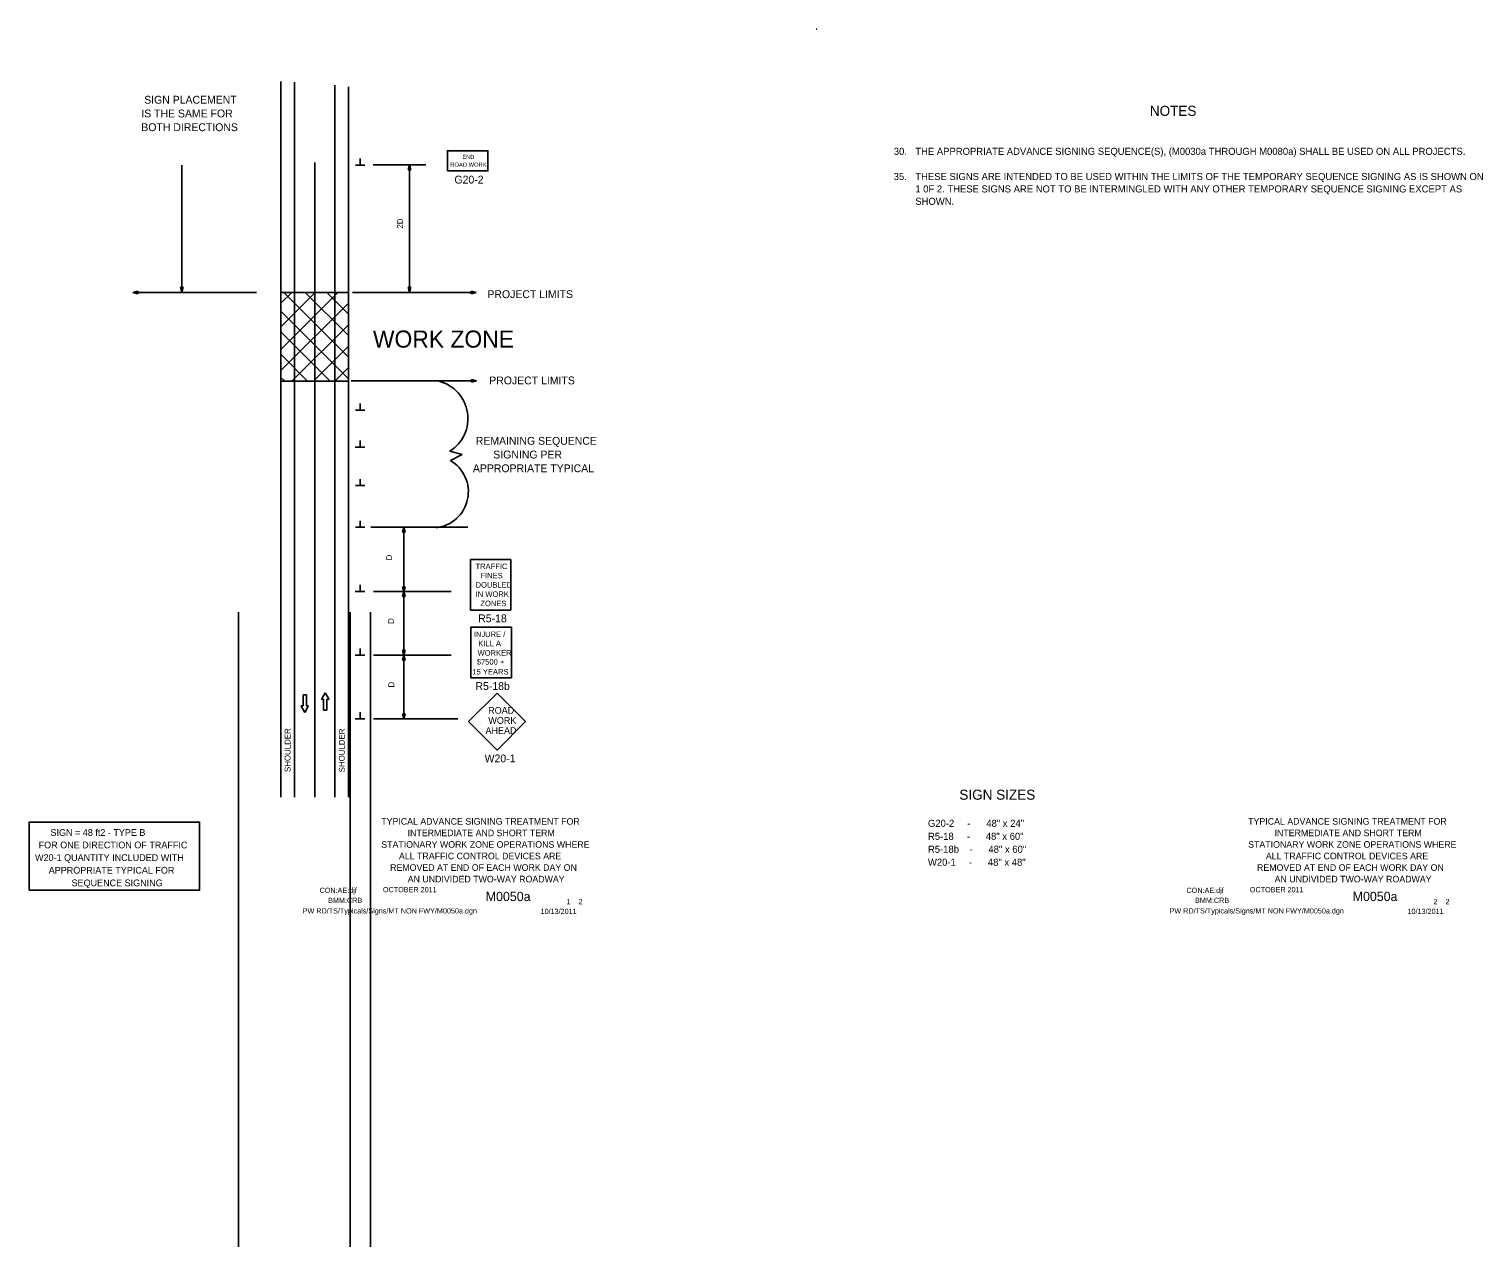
# Model space of a CAD drawing. Extents: x 16735 to 18461, y 5466 to 6911.
import ezdxf

# ---------------------------------------------------------------- set-up
doc = ezdxf.new("R2010")
doc.units = 0
for name, color, linetype in [('BORDER', 7, 'Continuous'), ('BORDER_SIGNAL_WO', 7, 'Continuous'), ('MT_SCRATCH_LEVEL_E', 7, 'Continuous'), ('PAVT_EDGE_EX', 7, 'Continuous'), ('TRAFFIC_SIGNS_PR', 7, 'Continuous'), ('TYPICAL_TEXT_DIMEN_PR', 7, 'Continuous')]:
    doc.layers.add(name, color=color, linetype=linetype)

msp = doc.modelspace()

# ---------------------------------------------------------------- linework, layer by layer
at = {"layer": 'BORDER'}
for p, q in [((17898.5, 5982.8), (17898.5, 5982.8)), ((17898.5, 5982.8), (17898.5, 5982.8)), ((17278, 5920.6), (17278, 5920.6))]:
    msp.add_line(p, q, dxfattribs=at)
at = {"layer": 'BORDER_SIGNAL_WO'}
msp.add_line((17670, 6911.2), (17669.5, 6911.3), dxfattribs=at)
at = {"layer": 'MT_SCRATCH_LEVEL_E'}
for p, q in [((17060.5, 6107.8), (17060.5, 6121)), ((17060.5, 6121), (17064.2, 6121)), ((17060.5, 6107.8), (17060.5, 6121)), ((17060.5, 6121), (17064.2, 6121)), ((17064.2, 6121), (17064.2, 6107.8)), ((17064.2, 6121), (17064.2, 6107.8)), ((17086.5, 6123.6), (17082.4, 6116.3)), ((17086.5, 6123.6), (17082.4, 6116.3)), ((17082.9, 6115.6), (17084.7, 6116)), ((17082.9, 6115.6), (17084.7, 6116)), ((17084.7, 6116), (17084.7, 6102.7)), ((17084.7, 6116), (17084.7, 6102.7)), ((17090.7, 6116.3), (17086.5, 6123.6)), ((17090.7, 6116.3), (17086.5, 6123.6)), ((17088.4, 6102.7), (17088.4, 6116)), ((17088.4, 6116), (17090.2, 6115.6)), ((17088.4, 6102.7), (17088.4, 6116)), ((17088.4, 6116), (17090.2, 6115.6)), ((17062.3, 6100.2), (17058.2, 6107.4)), ((17062.3, 6100.2), (17058.2, 6107.4)), ((17058.7, 6108.1), (17060.5, 6107.8)), ((17058.7, 6108.1), (17060.5, 6107.8)), ((17066.5, 6107.4), (17062.3, 6100.2)), ((17066.5, 6107.4), (17062.3, 6100.2)), ((17064.2, 6107.8), (17066, 6108.1)), ((17064.2, 6107.8), (17066, 6108.1)), ((17084.7, 6102.7), (17088.4, 6102.7)), ((17084.7, 6102.7), (17088.4, 6102.7))]:
    msp.add_line(p, q, dxfattribs=at)
for centre, start, end in [((17082.8, 6116.1), 150.4248, 279.9638), ((17082.8, 6116.1), 150.4248, 279.9638), ((17090.3, 6116.1), 260.0362, 29.7731), ((17090.3, 6116.1), 260.0362, 29.7731), ((17058.6, 6107.6), 80.0362, 209.5752), ((17058.6, 6107.6), 80.0362, 209.5752), ((17066.1, 6107.6), 330.2269, 99.9638), ((17066.1, 6107.6), 330.2269, 99.9638)]:
    msp.add_arc(centre, 0.463, start, end, dxfattribs=at)
at = {"layer": 'PAVT_EDGE_EX'}
for p, q in [((17034.1, 6849.3), (17034.1, 5999.6)), ((17050.1, 6848.5), (17050.1, 5999.6)), ((17098.1, 6844.8), (17098.1, 5999.6)), ((17114.1, 6842.6), (17114.1, 5999.6)), ((17050.1, 6753), (17050.1, 5999.6)), ((17074.1, 6753), (17074.1, 5999.6)), ((17114.1, 6598.8), (17034.1, 6598.8)), ((17034.1, 6586.1), (17046.8, 6598.8)), ((17034.1, 6557.8), (17074.8, 6598.6)), ((17034.6, 6531.8), (17101.6, 6598.8)), ((17114.1, 6522), (17037.1, 6599)), ((17114.1, 6547.5), (17062.5, 6599)), ((17114.1, 6572.9), (17088.4, 6598.7)), ((17098.1, 6599.3), (17098.1, 6493.5)), ((17114.1, 6598.4), (17113.7, 6598.8)), ((17114.1, 6493.5), (17114.1, 6598.8)), ((17114, 6496.6), (17033.7, 6577)), ((17034.5, 6506.3), (17114.1, 6585.9)), ((17047.3, 6493.6), (17114.1, 6560.4)), ((17092.2, 6493.6), (17034.4, 6551.5)), ((17065.7, 6493.5), (17034, 6525.3)), ((17072.6, 6493.5), (17114.1, 6534.9)), ((17098.1, 6493.5), (17114.1, 6509.5)), ((17033.6, 6493.5), (17114.1, 6493.5)), ((17038.2, 6493.7), (17034, 6497.9)), ((17098.1, 6493.5), (17114.1, 6493.5)), ((17098.1, 6493.5), (17098.1, 6493.5)), ((16983.7, 6219.1), (16983.7, 5465.7)), ((17116.3, 6219.1), (17116.3, 5465.7)), ((17140.3, 6219.1), (17140.3, 5465.7))]:
    msp.add_line(p, q, dxfattribs=at)
for points in [[(17050.1, 6753), (17050.1, 6728)], [(17074.1, 6753), (17074.1, 6728)], [(17074.1, 6653), (17074.1, 6628)], [(17074.1, 6453), (17074.1, 6428)], [(17074.1, 6353), (17074.1, 6328)], [(17074.1, 6253), (17074.1, 6228)], [(17050.1, 6153), (17050.1, 6128)], [(17074.1, 6153), (17074.1, 6128)], [(17050.1, 6053), (17050.1, 6028)], [(17074.1, 6053), (17074.1, 6028)]]:
    msp.add_lwpolyline(points, dxfattribs=at)
at = {"layer": 'TRAFFIC_SIGNS_PR'}
for p, q in [((17259, 6221.5), (17259, 6281.5)), ((17259, 6281.5), (17307, 6281.5)), ((17307, 6221.5), (17307, 6281.5)), ((17259, 6221.5), (17307, 6221.5)), ((17259.6, 6141.2), (17259.6, 6201.2)), ((17307.6, 6201.2), (17259.6, 6201.2)), ((17307.6, 6141.2), (17307.6, 6201.2)), ((17307.6, 6141.2), (17259.6, 6141.2)), ((17290.6, 6123.1), (17256.7, 6089.2)), ((17324.5, 6089.2), (17290.6, 6123.1)), ((17256.7, 6089.2), (17290.6, 6055.2)), ((17290.6, 6055.2), (17324.5, 6089.2))]:
    msp.add_line(p, q, dxfattribs=at)
at = {"layer": 'TYPICAL_TEXT_DIMEN_PR'}
for p, q in [((16916.5, 6749.9), (16916.5, 6599.1)), ((17128.1, 6749.8), (17122.5, 6749.8)), ((17128.1, 6749.8), (17128.1, 6757.6)), ((17133.7, 6749.8), (17128.1, 6749.8)), ((17143.5, 6750), (17205.9, 6750)), ((17185, 6744.2), (17186.6, 6750.1)), ((17186.5, 6749.9), (17186.5, 6599.1)), ((17186.6, 6750.1), (17188.1, 6744.2)), ((17186.6, 6744.2), (17185, 6744.2)), ((17188.1, 6744.2), (17186.6, 6744.2)), ((16864.1, 6600.4), (16858.2, 6598.8)), ((17005, 6598.8), (16858.2, 6598.8)), ((16858.2, 6598.8), (16864.1, 6597.2)), ((16864.1, 6598.8), (16864.1, 6600.4)), ((16864.1, 6597.2), (16864.1, 6598.8)), ((16916.5, 6599.1), (16914.9, 6605)), ((16914.9, 6605), (16916.5, 6605)), ((16916.5, 6605), (16918.1, 6605)), ((16918.1, 6605), (16916.5, 6599.1)), ((17119, 6598.8), (17265.8, 6598.8)), ((17186.6, 6598.9), (17185, 6604.8)), ((17185, 6604.8), (17186.6, 6604.8)), ((17186.6, 6604.8), (17188.1, 6604.8)), ((17188.1, 6604.8), (17186.6, 6598.9)), ((17259.9, 6598.8), (17259.9, 6600.4)), ((17259.9, 6600.4), (17265.8, 6598.8)), ((17265.8, 6598.8), (17259.9, 6597.2)), ((17259.9, 6597.2), (17259.9, 6598.8)), ((17117.5, 6493.9), (17266.2, 6493.9)), ((17260.4, 6493.9), (17260.4, 6495.4)), ((17260.4, 6495.4), (17266.2, 6493.9)), ((17266.2, 6493.9), (17260.4, 6492.3)), ((17260.4, 6492.3), (17260.4, 6493.9)), ((17128.2, 6458.9), (17122.6, 6458.9)), ((17128.2, 6458.9), (17128.2, 6466.7)), ((17133.8, 6458.9), (17128.2, 6458.9)), ((17127.9, 6415), (17127.9, 6422.8)), ((17127.9, 6415), (17122.3, 6415)), ((17133.5, 6415), (17127.9, 6415)), ((17234.6, 6410.2), (17249.2, 6406.4)), ((17249.2, 6406.4), (17235.2, 6399.3)), ((17128.2, 6369.4), (17122.6, 6369.4)), ((17128.2, 6369.4), (17128.2, 6377.2)), ((17133.8, 6369.4), (17128.2, 6369.4)), ((17128.2, 6319.9), (17122.6, 6319.9)), ((17128.2, 6319.9), (17128.2, 6327.7)), ((17133.8, 6319.9), (17128.2, 6319.9)), ((17140.6, 6319.9), (17255.8, 6319.9)), ((17178.2, 6314.1), (17179.8, 6319.9)), ((17179.8, 6319.9), (17179.8, 6168.1)), ((17179.8, 6319.9), (17181.4, 6314.1)), ((17179.8, 6314.1), (17178.2, 6314.1)), ((17181.4, 6314.1), (17179.8, 6314.1)), ((17127.9, 6243.7), (17127.9, 6251.5)), ((17179.8, 6243.5), (17178.2, 6249.4)), ((17178.2, 6249.4), (17179.8, 6249.4)), ((17179.8, 6249.4), (17181.4, 6249.4)), ((17181.4, 6249.4), (17179.8, 6243.5)), ((17127.9, 6243.7), (17122.3, 6243.7)), ((17133.5, 6243.7), (17127.9, 6243.7)), ((17144, 6243.5), (17236.1, 6243.5)), ((17178.2, 6237.6), (17179.8, 6243.5)), ((17179.8, 6237.6), (17178.2, 6237.6)), ((17179.8, 6243.5), (17181.4, 6237.6)), ((17181.4, 6237.6), (17179.8, 6237.6)), ((17127.9, 6168.3), (17122.3, 6168.3)), ((17127.9, 6168.3), (17127.9, 6176.1)), ((17133.5, 6168.3), (17127.9, 6168.3)), ((17144, 6168.1), (17236.1, 6168.1)), ((17179.8, 6168.1), (17178.2, 6174)), ((17178.2, 6174), (17179.8, 6174)), ((17178.2, 6162.2), (17179.8, 6168.1)), ((17179.8, 6162.2), (17178.2, 6162.2)), ((17179.8, 6174), (17181.4, 6174)), ((17181.4, 6174), (17179.8, 6168.1)), ((17179.8, 6168.1), (17179.8, 6092.7)), ((17179.8, 6168.1), (17181.4, 6162.2)), ((17181.4, 6162.2), (17179.8, 6162.2)), ((17127.9, 6092.5), (17122.3, 6092.5)), ((17127.9, 6092.5), (17127.9, 6100.3)), ((17133.6, 6092.5), (17127.9, 6092.5)), ((17144, 6092.7), (17244.2, 6092.7)), ((17179.8, 6092.7), (17178.2, 6098.6)), ((17178.2, 6098.6), (17179.8, 6098.6)), ((17179.8, 6098.6), (17181.4, 6098.6)), ((17181.4, 6098.6), (17179.8, 6092.7))]:
    msp.add_line(p, q, dxfattribs=at)
for points in [[(17231.7, 6743), (17279.7, 6743), (17279.7, 6767), (17231.7, 6767)], [(16735.1, 5889.1), (16937.5, 5889.1), (16937.5, 5970), (16735.1, 5970)]]:
    msp.add_lwpolyline(points, close=True, dxfattribs=at)
for centre, radius, start, end in [((17210.2, 6449), 45.8, 302.1563, 75.2517), ((17213.6, 6362.1), 42.9, 276.3375, 59.9789)]:
    msp.add_arc(centre, radius, start, end, dxfattribs=at)

# ---------------------------------------------------------------- texts
at = {"layer": 'BORDER_SIGNAL_WO'}
for s, height, p in [('TYPICAL ADVANCE SIGNING TREATMENT FOR', 7.812, (17153.1, 5966.9)), ('TYPICAL ADVANCE SIGNING TREATMENT FOR', 7.812, (18182.1, 5966.9)), ('INTERMEDIATE AND SHORT TERM ', 7.812, (17184.4, 5953.2)), ('INTERMEDIATE AND SHORT TERM ', 7.812, (18213.4, 5953.2)), ('STATIONARY WORK ZONE OPERATIONS WHERE', 7.812, (17153.1, 5939.5)), ('STATIONARY WORK ZONE OPERATIONS WHERE', 7.812, (18182.1, 5939.5)), ('REMOVED AT END OF EACH WORK DAY ON', 7.812, (17163.6, 5912.1)), ('ALL TRAFFIC CONTROL DEVICES ARE', 7.812, (17174.1, 5925.8)), ('REMOVED AT END OF EACH WORK DAY ON', 7.812, (18192.6, 5912.1)), ('ALL TRAFFIC CONTROL DEVICES ARE', 7.812, (18203.1, 5925.8)), ('AN UNDIVIDED TWO-WAY ROADWAY', 7.812, (17184.5, 5898.4)), ('AN UNDIVIDED TWO-WAY ROADWAY', 7.812, (18213.5, 5898.4)), ('CON:AE:djf', 6.2, (17079.9, 5885.9)), ('    OCTOBER 2011    ', 6.2, (17145.6, 5886.7)), ('    M0050a   ', 11, (17260.8, 5876.2)), ('CON:AE:djf', 6.2, (18108.9, 5885.9)), ('    OCTOBER 2011    ', 6.2, (18174.6, 5886.7)), ('    M0050a   ', 11, (18289.8, 5876.2)), ('PW RD/TS/Typicals/Signs/MT NON FWY/M0050a.dgn  ', 6.2, (17059.8, 5861.5)), ('BMM:CRB   ', 6.2, (17090.1, 5874)), ('10/13/2011    ', 6.2, (17342.2, 5860.9)), (' 1    2 ', 6.2, (17370.7, 5872.5)), ('PW RD/TS/Typicals/Signs/MT NON FWY/M0050a.dgn  ', 6.2, (18088.8, 5861.5)), ('BMM:CRB   ', 6.2, (18119.1, 5874)), ('10/13/2011    ', 6.2, (18371.2, 5860.9)), (' 2    2 ', 6.2, (18399.7, 5872.5))]:
    msp.add_text(s, height=height, dxfattribs=at).set_placement(p)
at = {"layer": 'TRAFFIC_SIGNS_PR'}
for s, height, p in [('SIGN PLACEMENT', 9.3, (16871.7, 6822.8)), ('BOTH DIRECTIONS', 9.3, (16868.3, 6790.2)), ('IS THE SAME FOR', 9.3, (16868.3, 6806.5)), ('G20-2', 9.3, (17240, 6728)), ('PROJECT LIMITS', 9.3, (17279.1, 6592)), ('PROJECT LIMITS', 9.3, (17281.3, 6489.6)), ('REMAINING SEQUENCE', 9.3, (17265.3, 6417.9)), ('SIGNING PER ', 9.3, (17286.1, 6401.6)), ('APPROPRIATE TYPICAL', 9.3, (17261.9, 6385.3)), ('TRAFFIC', 6.5, (17265, 6270.3)), ('FINES', 6.5, (17270.8, 6259.3)), ('DOUBLED', 6.5, (17265.1, 6248.3)), ('IN WORK', 6.5, (17265.2, 6237.3)), ('ZONES', 6.5, (17270.8, 6226.3)), ('R5-18', 9.3, (17268.2, 6207.2)), ('INJURE /', 6.5, (17263, 6189.7)), ('KILL A', 6.5, (17268.3, 6178.8)), ('$7500 +', 6.5, (17266.5, 6156.9)), ('WORKER', 6.5, (17267.4, 6167.6)), ('15 YEARS', 6.5, (17261.3, 6145.2)), ('R5-18b', 9.3, (17264.9, 6126.8)), ('WORK', 8, (17280.2, 6086.6)), ('ROAD', 8, (17280, 6098.6)), ('AHEAD', 8, (17276.8, 6074.6)), ('W20-1', 9.3, (17275.8, 6040.9))]:
    msp.add_text(s, height=height, dxfattribs=at).set_placement(p)
at = {"layer": 'TYPICAL_TEXT_DIMEN_PR'}
for s, height, p in [('NOTES', 12, (18065.4, 6808.3)), ('30.', 8.4, (17761.5, 6762)), ('THE APPROPRIATE ADVANCE SIGNING SEQUENCE(S), (M0030a THROUGH M0080a) SHALL BE USED ON ALL PROJECTS.', 8.4, (17787, 6762)), ('ROAD WORK', 4.96, (17235.1, 6747.9)), ('END', 4.79, (17249.5, 6757.3)), ('35.', 8.4, (17761.3, 6732.1)), ('THESE SIGNS ARE INTENDED TO BE USED WITHIN THE LIMITS OF THE TEMPORARY SEQUENCE SIGNING AS IS SHOWN ON ', 8.4, (17787, 6732.1)), ('1 0F 2. THESE SIGNS ARE NOT TO BE INTERMINGLED WITH ANY OTHER TEMPORARY SEQUENCE SIGNING EXCEPT AS', 8.4, (17787, 6717.4)), ('SHOWN.', 8.4, (17787, 6702.7)), ('WORK ZONE', 20.31, (17143.2, 6533.2)), ('SIGN SIZES', 12, (17839.3, 5996.5)), ('G20-2     -      48" x 24"', 8.4, (17802, 5964.3)), ('SIGN = 48 ft2 - TYPE B', 8, (16760.5, 5953.6)), ('R5-18     -      48" x 60"', 8.4, (17802, 5948.9)), ('FOR ONE DIRECTION OF TRAFFIC', 8, (16746.5, 5938.8)), ('R5-18b    -      48" x 60"', 8.4, (17802, 5933.5)), ('W20-1 QUANTITY INCLUDED WITH ', 8, (16742.2, 5923.8)), ('W20-1     -      48" x 48"', 8.4, (17802, 5918.1)), ('APPROPRIATE TYPICAL FOR ', 8, (16758.4, 5908.8)), ('SEQUENCE SIGNING', 8, (16785.5, 5893.8))]:
    msp.add_text(s, height=height, dxfattribs=at).set_placement(p)
for s, p in [('2D', (17178.8, 6674.5)), ('D', (17165.8, 6280.7)), ('D', (17168.1, 6205.2)), ('D', (17168.5, 6129.7)), ('SHOULDER', (17045.4, 6029.4)), ('SHOULDER', (17109.8, 6029))]:
    msp.add_text(s, height=7, rotation=90, dxfattribs=at).set_placement(p)

doc.saveas('drawing.dxf')
